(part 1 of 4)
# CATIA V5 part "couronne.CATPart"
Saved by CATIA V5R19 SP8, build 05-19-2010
Part number: couronne
Bounding box of the stored display mesh (mm): x 28.851 to 43.851, y 188.967 to 314.961, z 25.357 to 88.933
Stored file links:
  G:\EU_thinkMotion\CFAO_2010\MMS_groupe3\MMS_groupe3\A reprendre\amenand\amenand\couronne.CATPart
  F:\thinkmotion CFAO v12.1\essuie_glace.CATProduct
  G:\EU_thinkMotion\CFAO_2010\MMS_groupe3\MMS_groupe3\A reprendre\amenand\amenand\squelette_biellette3.CATPart
  CATDrawing1.CATDrawing
  G:\EU_thinkMotion\CFAO_2010\MMS_groupe3\MMS_groupe3\A reprendre\amenand\amenand\squelette_pignon.CATPart
  G:\EU_thinkMotion\CFAO_2010\MMS_groupe3\MMS_groupe3\A reprendre\amenand\amenand\bati.CATPart
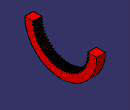
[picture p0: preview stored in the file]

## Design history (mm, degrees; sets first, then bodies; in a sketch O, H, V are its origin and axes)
Set1
  Plane1: linked copy from another document
  DatumCurve1 to DatumCurve3: linked copy from another document
Body1 (main body)
  Sketch1 on Plane1, origin (43.8512, 251.964, 88.354), H (0, 1, 0), V (0, 0, 1)
    point P1 (0, 0)
    line L1 (44.6312, -19.5831) -> (44.9349, -19.5977)
    line L2 (44.9349, -19.5977) -> (45.2527, -19.6074)
    line L3 (45.2527, -19.6074) -> (45.5845, -19.6118)
    line L4 (45.5845, -19.6118) -> (45.9303, -19.6103)
    line L5 (45.9303, -19.6103) -> (46.0835, -19.6069)
    arc A1 centre (46.029, -19.0968) radius 0.513 from (46.0835, -19.6069) to (46.1004, -19.6048) ccw
    arc A2 centre (45.9892, -19.104) radius 0.513 from (46.1004, -19.6048) to (46.1884, -19.5768) ccw
    arc A3 centre (45.9631, -19.1159) radius 0.513 from (46.1884, -19.5768) to (46.369, -19.4296) ccw
    arc A4 centre (45.9505, -19.1329) radius 0.513 from (46.369, -19.4296) to (46.419, -19.3418) ccw
    arc A5 centre (0, 0) radius 50.2875 from (46.419, -19.3419) to (46.5028, -19.1397) ccw
    arc A6 centre (46.0177, -18.9727) radius 0.513 from (46.5028, -19.1397) to (46.5269, -18.9102) ccw
    arc A7 centre (46.0212, -18.9965) radius 0.513 from (46.5269, -18.9102) to (46.4782, -18.7634) ccw
    arc A8 centre (46.0378, -19.0265) radius 0.513 from (46.4782, -18.7634) to (46.4517, -18.7234) ccw
    arc A9 centre (46.0672, -19.063) radius 0.513 from (46.4517, -18.7234) to (46.4347, -18.7051) ccw
    line L6 (46.4347, -18.7051) -> (46.2217, -18.4865)
    line L7 (46.2217, -18.4865) -> (45.9811, -18.248)
    line L8 (45.9811, -18.248) -> (45.7464, -18.0233)
    line L9 (45.7464, -18.0233) -> (45.5181, -17.8122)
    line L10 (45.5181, -17.8122) -> (45.2964, -17.6144)
    line L11 (45.2964, -17.6144) -> (45.0819, -17.4296)
    line L12 (45.0819, -17.4296) -> (44.8749, -17.2574)
    line L13 (44.8749, -17.2574) -> (44.6758, -17.0976)
    line L14 (44.6758, -17.0976) -> (44.4849, -16.9498)
    line L15 (44.4849, -16.9498) -> (44.3026, -16.8136)
    line L16 (44.3026, -16.8136) -> (44.1885, -16.7315)
    arc A10 centre (0, 0) radius 47.25 from (44.1885, -16.7315) to (44.605, -15.5869) ccw
    line L17 (44.605, -15.5869) -> (44.6371, -15.5896)
    line L18 (44.6371, -15.5896) -> (44.8572, -15.604)
    line L19 (44.8572, -15.604) -> (45.0914, -15.6153)
    line L20 (45.0914, -15.6153) -> (45.3396, -15.6228)
    line L21 (45.3396, -15.6228) -> (45.6019, -15.6263)
    line L22 (45.6019, -15.6263) -> (45.8781, -15.6251)
    line L23 (45.8781, -15.6251) -> (46.1681, -15.6187)
    line L24 (46.1681, -15.6187) -> (46.4719, -15.6068)
    line L25 (46.4719, -15.6068) -> (46.7894, -15.5888)
    line L26 (46.7894, -15.5888) -> (47.1203, -15.5642)
    line L27 (47.1203, -15.5642) -> (47.4646, -15.5326)
    line L28 (47.4646, -15.5326) -> (47.617, -15.5159)
    arc A11 centre (47.5182, -15.0125) radius 0.513 from (47.617, -15.5159) to (47.6336, -15.5123) ccw
    arc A12 centre (47.4792, -15.0231) radius 0.513 from (47.6336, -15.5123) to (47.7189, -15.4767) ccw
    arc A13 centre (47.4543, -15.0372) radius 0.513 from (47.7189, -15.4767) to (47.886, -15.3143) ccw
    arc A14 centre (47.4432, -15.0553) radius 0.513 from (47.886, -15.3143) to (47.9281, -15.2225) ccw
    arc A15 centre (0, 0) radius 50.2875 from (47.9281, -15.2225) to (47.9939, -15.0139) ccw
    arc A16 centre (47.4962, -14.8898) radius 0.513 from (47.9939, -15.0139) to (47.998, -14.7831) ccw
    arc A17 centre (47.5017, -14.9132) radius 0.513 from (47.998, -14.7831) to (47.9366, -14.6411) ccw
    arc A18 centre (47.5208, -14.9416) radius 0.513 from (47.9366, -14.6411) to (47.9068, -14.6036) ccw
    arc A19 centre (47.5534, -14.9755) radius 0.513 from (47.9068, -14.6036) to (47.8882, -14.5869) ccw
    line L29 (47.8882, -14.5869) -> (47.6571, -14.3877)
    line L30 (47.6571, -14.3877) -> (47.3966, -14.171)
    line L31 (47.3966, -14.171) -> (47.1432, -13.9677)
    line L32 (47.1432, -13.9677) -> (46.8973, -13.7773)
    line L33 (46.8973, -13.7773) -> (46.6593, -13.5995)
    line L34 (46.6593, -13.5995) -> (46.4295, -13.4341)
    line L35 (46.4295, -13.4341) -> (46.2082, -13.2806)
    line L36 (46.2082, -13.2806) -> (45.9959, -13.1388)
    line L37 (45.9959, -13.1388) -> (45.7929, -13.0081)
    line L38 (45.7929, -13.0081) -> (45.5994, -12.8884)
    line L39 (45.5994, -12.8884) -> (45.4786, -12.8165)
    arc A20 centre (0, 0) radius 47.25 from (45.4786, -12.8165) to (45.7938, -11.64) ccw
    line L40 (45.7938, -11.64) -> (45.8259, -11.6399)
    line L41 (45.8259, -11.6399) -> (46.0464, -11.6351)
    line L42 (46.0464, -11.6351) -> (46.2807, -11.6259)
    line L43 (46.2807, -11.6259) -> (46.5287, -11.6118)
    line L44 (46.5287, -11.6118) -> (46.7903, -11.5923)
    line L45 (46.7903, -11.5923) -> (47.0653, -11.5671)
    line L46 (47.0653, -11.5671) -> (47.3537, -11.5355)
    line L47 (47.3537, -11.5355) -> (47.6553, -11.4971)
    line L48 (47.6553, -11.4971) -> (47.97, -11.4515)
    line L49 (47.97, -11.4515) -> (48.2975, -11.3982)
    line L50 (48.2975, -11.3982) -> (48.6378, -11.3366)
    line L51 (48.6378, -11.3366) -> (48.7881, -11.3067)
    arc A21 centre (48.6458, -10.8139) radius 0.513 from (48.7881, -11.3067) to (48.8043, -11.3017) ccw
    arc A22 centre (48.6079, -10.8278) radius 0.513 from (48.8043, -11.3017) to (48.8862, -11.2588) ccw
    arc A23 centre (48.5843, -10.8441) radius 0.513 from (48.8862, -11.2588) to (49.0385, -11.0825) ccw
    arc A24 centre (48.5748, -10.863) radius 0.513 from (49.0385, -11.0825) to (49.0725, -10.9874) ccw
    arc A25 centre (0, 0) radius 50.2875 from (49.0725, -10.9874) to (49.1198, -10.7738) ccw
    arc A26 centre (48.6132, -10.6935) radius 0.513 from (49.1198, -10.7738) to (49.1037, -10.5436) ccw
    arc A27 centre (48.6207, -10.7164) radius 0.513 from (49.1037, -10.5436) to (49.0303, -10.4075) ccw
    arc A28 centre (48.6423, -10.743) radius 0.513 from (49.0303, -10.4075) to (48.9973, -10.3727) ccw
    arc A29 centre (48.6776, -10.7739) radius 0.513 from (48.9973, -10.3727) to (48.9773, -10.3576) ccw
    line L52 (48.9773, -10.3576) -> (48.7297, -10.1793)
    line L53 (48.7297, -10.1793) -> (48.4513, -9.9862)
    line L54 (48.4513, -9.9862) -> (48.1812, -9.8057)
    line L55 (48.1812, -9.8057) -> (47.9196, -9.6375)
    line L56 (47.9196, -9.6375) -> (47.667, -9.4811)
    line L57 (47.667, -9.4811) -> (47.4236, -9.3364)
    line L58 (47.4236, -9.3364) -> (47.1899, -9.2028)
    line L59 (47.1899, -9.2028) -> (46.966, -9.0799)
    line L60 (46.966, -9.0799) -> (46.7523, -8.9675)
    line L61 (46.7523, -8.9675) -> (46.5492, -8.8651)
    line L62 (46.5492, -8.8651) -> (46.4225, -8.804)
    arc A30 centre (0, 0) radius 47.25 from (46.4225, -8.804) to (46.634, -7.6046) ccw
    line L63 (46.634, -7.6045) -> (46.666, -7.6016)
    line L64 (46.666, -7.6016) -> (46.8853, -7.5776)
    line L65 (46.8853, -7.5776) -> (47.1179, -7.548)
    line L66 (47.1179, -7.548) -> (47.3637, -7.5124)
    line L67 (47.3637, -7.5124) -> (47.6226, -7.4702)
    line L68 (47.6226, -7.4702) -> (47.8944, -7.421)
    line L69 (47.8944, -7.421) -> (48.1789, -7.3644)
    line L70 (48.1789, -7.3644) -> (48.476, -7.2999)
    line L71 (48.476, -7.2999) -> (48.7855, -7.2271)
    line L72 (48.7855, -7.2271) -> (49.1071, -7.1454)
    line L73 (49.1071, -7.1454) -> (49.4407, -7.0544)
    line L74 (49.4407, -7.0544) -> (49.5879, -7.0115)
    arc A31 centre (49.4032, -6.5329) radius 0.513 from (49.5879, -7.0115) to (49.6036, -7.0052) ccw
    arc A32 centre (49.3666, -6.5502) radius 0.513 from (49.6036, -7.0052) to (49.6814, -6.9552) ccw
    arc A33 centre (49.3445, -6.5684) radius 0.513 from (49.6814, -6.9552) to (49.8178, -6.7664) ccw
    arc A34 centre (49.3367, -6.5881) radius 0.513 from (49.8178, -6.7664) to (49.8434, -6.6686) ccw
    arc A35 centre (0, 0) radius 50.2875 from (49.8434, -6.6686) to (49.8719, -6.4517) ccw
    arc A36 centre (49.3602, -6.4159) radius 0.513 from (49.8719, -6.4517) to (49.8358, -6.2238) ccw
    arc A37 centre (49.3697, -6.438) radius 0.513 from (49.8358, -6.2238) to (49.7508, -6.0946) ccw
    arc A38 centre (49.3935, -6.4627) radius 0.513 from (49.7508, -6.0946) to (49.7149, -6.0629) ccw
    arc A39 centre (49.4314, -6.4904) radius 0.513 from (49.7149, -6.0629) to (49.6937, -6.0495) ccw
    line L75 (49.6937, -6.0495) -> (49.4314, -5.8935)
    line L76 (49.4314, -5.8935) -> (49.1373, -5.7254)
    line L77 (49.1373, -5.7254) -> (48.8524, -5.5691)
    line L78 (48.8524, -5.5691) -> (48.5772, -5.4243)
    line L79 (48.5772, -5.4243) -> (48.3119, -5.2906)
    line L80 (48.3119, -5.2906) -> (48.0569, -5.1676)
    line L81 (48.0569, -5.1676) -> (47.8124, -5.0549)
    line L82 (47.8124, -5.0549) -> (47.5787, -4.952)
    line L83 (47.5787, -4.952) -> (47.356, -4.8587)
    line L84 (47.356, -4.8587) -> (47.1447, -4.7744)
    line L85 (47.1447, -4.7744) -> (47.0132, -4.7245)
    arc A40 centre (0, 0) radius 47.25 from (47.0132, -4.7246) to (47.1194, -3.5112) ccw
    line L86 (47.1194, -3.5112) -> (47.151, -3.5055)
    line L87 (47.151, -3.5055) -> (47.3673, -3.4624)
    line L88 (47.3673, -3.4624) -> (47.5964, -3.4127)
    line L89 (47.5964, -3.4127) -> (47.8382, -3.3558)
    line L90 (47.8382, -3.3558) -> (48.0924, -3.2912)
    line L91 (48.0924, -3.2912) -> (48.3589, -3.2185)
    line L92 (48.3589, -3.2185) -> (48.6374, -3.1374)
    line L93 (48.6374, -3.1374) -> (48.9278, -3.0472)
    line L94 (48.9278, -3.0472) -> (49.2297, -2.9476)
    line L95 (49.2297, -2.9476) -> (49.543, -2.8382)
    line L96 (49.543, -2.8382) -> (49.8674, -2.7185)
    line L97 (49.8674, -2.7185) -> (50.0103, -2.663)
    arc A41 centre (49.7846, -2.2023) radius 0.513 from (50.0103, -2.663) to (50.0254, -2.6553) ccw
    arc A42 centre (49.7497, -2.2227) radius 0.513 from (50.0254, -2.6553) to (50.0986, -2.5988) ccw
    arc A43 centre (49.7292, -2.2428) radius 0.513 from (50.0986, -2.5988) to (50.2179, -2.3987) ccw
    arc A44 centre (49.7232, -2.2631) radius 0.513 from (50.2179, -2.3987) to (50.2349, -2.2991) ccw
    arc A45 centre (0, 0) radius 50.2875 from (50.2349, -2.2991) to (50.2444, -2.0805) ccw
    arc A46 centre (49.7315, -2.0895) radius 0.513 from (50.2444, -2.0805) to (50.1886, -1.8566) ccw
    arc A47 centre (49.743, -2.1107) radius 0.513 from (50.1886, -1.8566) to (50.0926, -1.7353) ccw
    arc A48 centre (49.7688, -2.1332) radius 0.513 from (50.0926, -1.7353) to (50.0541, -1.7068) ccw
    arc A49 centre (49.809, -2.1575) radius 0.513 from (50.0541, -1.7068) to (50.0318, -1.6954) ccw
    line L98 (50.0318, -1.6954) -> (49.757, -1.5629)
    line L99 (49.757, -1.5629) -> (49.4493, -1.421)
    line L100 (49.4493, -1.421) -> (49.1519, -1.2902)
    line L101 (49.1519, -1.2902) -> (48.8651, -1.1699)
    line L102 (48.8651, -1.1699) -> (48.5892, -1.0598)
    line L103 (48.5892, -1.0598) -> (48.3244, -0.9595)
    line L104 (48.3244, -0.9595) -> (48.071, -0.8685)
    line L105 (48.071, -0.8685) -> (47.8292, -0.7864)
    line L106 (47.8292, -0.7864) -> (47.5993, -0.7128)
    line L107 (47.5993, -0.7128) -> (47.3814, -0.6473)
    line L108 (47.3814, -0.6473) -> (47.2461, -0.6091)
    arc A50 centre (0, 0) radius 47.25 from (47.2461, -0.6091) to (47.248, 0.434) ccw
    arc A51 centre (0, 0) radius 47.25 from (-47.248, -0.434) to (-47.2461, -0.6089) ccw
    line L109 (-47.2461, -0.6089) -> (-47.2771, -0.6174)
    line L110 (-47.2771, -0.6174) -> (-47.4888, -0.6791)
    line L111 (-47.4888, -0.6791) -> (-47.7127, -0.7486)
    line L112 (-47.7127, -0.7486) -> (-47.9486, -0.8264)
    line L113 (-47.9486, -0.8264) -> (-48.1963, -0.9129)
    line L114 (-48.1963, -0.9129) -> (-48.4554, -1.0085)
    line L115 (-48.4554, -1.0085) -> (-48.7258, -1.1136)
    line L116 (-48.7258, -1.1136) -> (-49.0072, -1.2287)
    line L117 (-49.0072, -1.2287) -> (-49.2993, -1.3542)
    line L118 (-49.2993, -1.3542) -> (-49.6019, -1.4905)
    line L119 (-49.6019, -1.4905) -> (-49.9146, -1.638)
    line L120 (-49.9146, -1.638) -> (-50.0521, -1.7058)
    arc A52 centre (-49.7871, -2.1451) radius 0.513 from (-50.0521, -1.7058) to (-50.0665, -1.7148) ccw
    arc A53 centre (-49.7541, -2.1217) radius 0.513 from (-50.0665, -1.7148) to (-50.1344, -1.7775) ccw
    arc A54 centre (-49.7354, -2.1) radius 0.513 from (-50.1344, -1.7775) to (-50.2359, -1.9872) ccw
    arc A55 centre (-49.7312, -2.0792) radius 0.513 from (-50.2359, -1.9872) to (-50.2441, -2.0879) ccw
    arc A56 centre (0, 0) radius 50.2875 from (-50.2441, -2.0879) to (-50.2346, -2.3065) ccw
    arc A57 centre (-49.7244, -2.2528) radius 0.513 from (-50.2346, -2.3065) to (-50.1595, -2.5247) ccw
    arc A58 centre (-49.7376, -2.2327) radius 0.513 from (-50.1595, -2.5247) to (-50.0532, -2.6371) ccw
    arc A59 centre (-49.7653, -2.2126) radius 0.513 from (-50.0532, -2.6371) to (-50.0124, -2.6622) ccw
    arc A60 centre (-49.8075, -2.1919) radius 0.513 from (-50.0124, -2.6622) to (-49.9892, -2.6716) ccw
    line L121 (-49.9892, -2.6716) -> (-49.7039, -2.7797)
    line L122 (-49.7039, -2.7797) -> (-49.385, -2.8942)
    line L123 (-49.385, -2.8942) -> (-49.0773, -2.9986)
    line L124 (-49.0773, -2.9986) -> (-48.7811, -3.0934)
    line L125 (-48.7811, -3.0934) -> (-48.4967, -3.179)
    line L126 (-48.4967, -3.179) -> (-48.2241, -3.2559)
    line L127 (-48.2241, -3.2559) -> (-47.9638, -3.3245)
    line L128 (-47.9638, -3.3245) -> (-47.7157, -3.3851)
    line L129 (-47.7157, -3.3851) -> (-47.4803, -3.4384)
    line L130 (-47.4803, -3.4384) -> (-47.2575, -3.4848)
    line L131 (-47.2575, -3.4848) -> (-47.1194, -3.511)
    arc A61 centre (0, 0) radius 47.25 from (-47.1194, -3.511) to (-47.0132, -4.7244) ccw
    line L132 (-47.0132, -4.7244) -> (-47.0434, -4.7355)
    line L133 (-47.0434, -4.7355) -> (-47.2489, -4.8154)
    line L134 (-47.2489, -4.8154) -> (-47.4659, -4.9042)
    line L135 (-47.4659, -4.9042) -> (-47.6941, -5.0022)
    line L136 (-47.6941, -5.0022) -> (-47.9333, -5.11)
    line L137 (-47.9333, -5.11) -> (-48.1831, -5.2278)
    line L138 (-48.1831, -5.2278) -> (-48.4433, -5.3561)
    line L139 (-48.4433, -5.3561) -> (-48.7136, -5.4953)
    line L140 (-48.7136, -5.4953) -> (-48.9937, -5.6458)
    line L141 (-48.9937, -5.6458) -> (-49.2832, -5.808)
    line L142 (-49.2832, -5.808) -> (-49.5819, -5.9822)
    line L143 (-49.5819, -5.9822) -> (-49.713, -6.0617)
    arc A62 centre (-49.4107, -6.4762) radius 0.513 from (-49.713, -6.0617) to (-49.7265, -6.0719) ccw
    arc A63 centre (-49.3798, -6.45) radius 0.513 from (-49.7265, -6.0719) to (-49.7887, -6.1403) ccw
    arc A64 centre (-49.3632, -6.4267) radius 0.513 from (-49.7887, -6.1403) to (-49.8715, -6.358) ccw
    arc A65 centre (-49.3608, -6.4057) radius 0.513 from (-49.8715, -6.358) to (-49.871, -6.459) ccw
    arc A66 centre (0, 0) radius 50.2875 from (-49.871, -6.459) to (-49.8424, -6.6759) ccw
    arc A67 centre (-49.3388, -6.578) radius 0.513 from (-49.8424, -6.6759) to (-49.7485, -6.8867) ccw
    arc A68 centre (-49.3538, -6.5591) radius 0.513 from (-49.7485, -6.8867) to (-49.6329, -6.9895) ccw
    arc A69 centre (-49.3831, -6.5415) radius 0.513 from (-49.6329, -6.9895) to (-49.59, -7.0109) ccw
    arc A70 centre (-49.4269, -6.5245) radius 0.513 from (-49.59, -7.0109) to (-49.5661, -7.0183) ccw
    line L144 (-49.5661, -7.0183) -> (-49.2725, -7.1011)
    line L145 (-49.2725, -7.1011) -> (-48.9448, -7.1873)
    line L146 (-48.9448, -7.1873) -> (-48.6292, -7.2646)
    line L147 (-48.6292, -7.2646) -> (-48.3259, -7.3332)
    line L148 (-48.3259, -7.3332) -> (-48.0351, -7.3937)
    line L149 (-48.0351, -7.3937) -> (-47.7569, -7.4465)
    line L150 (-47.7569, -7.4465) -> (-47.4915, -7.4921)
    line L151 (-47.4915, -7.4921) -> (-47.2391, -7.531)
    line L152 (-47.2391, -7.531) -> (-46.9999, -7.5635)
    line L153 (-46.9999, -7.5635) -> (-46.774, -7.5903)
    line L154 (-46.774, -7.5903) -> (-46.6341, -7.6043)
    arc A71 centre (0, 0) radius 47.25 from (-46.6341, -7.6044) to (-46.4226, -8.8039) ccw
    line L155 (-46.4226, -8.8039) -> (-46.4516, -8.8176)
    line L156 (-46.4516, -8.8176) -> (-46.6494, -8.9151)
    line L157 (-46.6494, -8.9151) -> (-46.8579, -9.0225)
    line L158 (-46.8579, -9.0225) -> (-47.0767, -9.14)
    line L159 (-47.0767, -9.14) -> (-47.3055, -9.2682)
    line L160 (-47.3055, -9.2682) -> (-47.5441, -9.4073)
    line L161 (-47.5441, -9.4073) -> (-47.7922, -9.5578)
    line L162 (-47.7922, -9.5578) -> (-48.0493, -9.7201)
    line L163 (-48.0493, -9.7201) -> (-48.3152, -9.8944)
    line L164 (-48.3152, -9.8944) -> (-48.5895, -10.0812)
    line L165 (-48.5895, -10.0812) -> (-48.8719, -10.2807)
    line L166 (-48.8719, -10.2807) -> (-48.9955, -10.3714)
    arc A72 centre (-48.6582, -10.7579) radius 0.513 from (-48.9955, -10.3714) to (-49.0081, -10.3827) ccw
    arc A73 centre (-48.6298, -10.7292) radius 0.513 from (-49.0081, -10.3827) to (-49.0641, -10.4563) ccw
    arc A74 centre (-48.6152, -10.7045) radius 0.513 from (-49.0641, -10.4563) to (-49.1276, -10.6804) ccw
    arc A75 centre (-48.6146, -10.6834) radius 0.513 from (-49.1276, -10.6804) to (-49.1183, -10.781) ccw
    arc A76 centre (0, 0) radius 50.2875 from (-49.1183, -10.781) to (-49.0709, -10.9946) ccw
    arc A77 centre (-48.5778, -10.8532) radius 0.513 from (-49.0709, -10.9946) to (-48.959, -11.1964) ccw
    arc A78 centre (-48.5943, -10.8356) radius 0.513 from (-48.959, -11.1964) to (-48.8349, -11.2887) ccw
    arc A79 centre (-48.6251, -10.8206) radius 0.513 from (-48.8349, -11.2887) to (-48.7903, -11.3063) ccw
    arc A80 centre (-48.6702, -10.8075) radius 0.513 from (-48.7903, -11.3063) to (-48.7658, -11.3115) ccw
    line L167 (-48.7658, -11.3115) -> (-48.4661, -11.3684)
    line L168 (-48.4661, -11.3684) -> (-48.1321, -11.4258)
    line L169 (-48.1321, -11.4258) -> (-47.811, -11.4752)
    line L170 (-47.811, -11.4752) -> (-47.5029, -11.5172)
    line L171 (-47.5029, -11.5172) -> (-47.2079, -11.5521)
    line L172 (-47.2079, -11.5521) -> (-46.9261, -11.5805)
    line L173 (-46.9261, -11.5805) -> (-46.6578, -11.6028)
    line L174 (-46.6578, -11.6028) -> (-46.403, -11.6195)
    line L175 (-46.403, -11.6195) -> (-46.1619, -11.631)
    line L176 (-46.1619, -11.631) -> (-45.9345, -11.638)
    line L177 (-45.9345, -11.638) -> (-45.7938, -11.6398)
    arc A81 centre (0, 0) radius 47.25 from (-45.7939, -11.6398) to (-45.4786, -12.8163) ccw
    line L178 (-45.4786, -12.8163) -> (-45.5064, -12.8325)
    line L179 (-45.5064, -12.8325) -> (-45.6949, -12.9469)
    line L180 (-45.6949, -12.9469) -> (-45.8932, -13.0721)
    line L181 (-45.8932, -13.0721) -> (-46.1009, -13.2083)
    line L182 (-46.1009, -13.2083) -> (-46.3177, -13.3559)
    line L183 (-46.3177, -13.3559) -> (-46.5433, -13.5153)
    line L184 (-46.5433, -13.5153) -> (-46.7773, -13.6868)
    line L185 (-46.7773, -13.6868) -> (-47.0193, -13.8709)
    line L186 (-47.0193, -13.8709) -> (-47.269, -14.0677)
    line L187 (-47.269, -14.0677) -> (-47.526, -14.2777)
    line L188 (-47.526, -14.2777) -> (-47.7899, -14.5011)
    line L189 (-47.7899, -14.5011) -> (-47.9051, -14.6021)
    arc A82 centre (-47.5354, -14.9578) radius 0.513 from (-47.9051, -14.6021) to (-47.9167, -14.6146) ccw
    arc A83 centre (-47.5096, -14.9268) radius 0.513 from (-47.9167, -14.6146) to (-47.9661, -14.6927) ccw
    arc A84 centre (-47.4972, -14.9009) radius 0.513 from (-47.9661, -14.6927) to (-48.0098, -14.9215) ccw
    arc A85 centre (-47.4985, -14.8798) radius 0.513 from (-48.0098, -14.9215) to (-47.9917, -15.0209) ccw
    arc A86 centre (0, 0) radius 50.2875 from (-47.9917, -15.0209) to (-47.9259, -15.2296) ccw
    arc A87 centre (-47.447, -15.0457) radius 0.513 from (-47.9259, -15.2296) to (-47.7969, -15.4209) ccw
    arc A88 centre (-47.465, -15.0297) radius 0.513 from (-47.7969, -15.4209) to (-47.6652, -15.502) ccw
    arc A89 centre (-47.497, -15.0174) radius 0.513 from (-47.6652, -15.502) to (-47.6192, -15.5156) ccw
    arc A90 centre (-47.543, -15.0083) radius 0.513 from (-47.6192, -15.5156) to (-47.5944, -15.5187) ccw
    line L190 (-47.5944, -15.5187) -> (-47.2908, -15.5493)
    line L191 (-47.2908, -15.5493) -> (-46.9532, -15.5773)
    line L192 (-46.9532, -15.5773) -> (-46.629, -15.5986)
    line L193 (-46.629, -15.5986) -> (-46.3183, -15.6135)
    line L194 (-46.3183, -15.6135) -> (-46.0214, -15.6226)
    line L195 (-46.0214, -15.6226) -> (-45.7383, -15.6263)
    line L196 (-45.7383, -15.6263) -> (-45.469, -15.6251)
    line L197 (-45.469, -15.6251) -> (-45.2137, -15.6195)
    line L198 (-45.2137, -15.6195) -> (-44.9725, -15.6101)
    line L199 (-44.9725, -15.6101) -> (-44.7453, -15.5972)
    line L200 (-44.7453, -15.5972) -> (-44.6051, -15.5867)
    arc A91 centre (0, 0) radius 47.25 from (-44.6051, -15.5867) to (-44.1885, -16.7313) ccw
    line L201 (-44.1885, -16.7313) -> (-44.2148, -16.7498)
    line L202 (-44.2148, -16.7498) -> (-44.3926, -16.8803)
    line L203 (-44.3926, -16.8803) -> (-44.5793, -17.0222)
    line L204 (-44.5793, -17.0222) -> (-44.7743, -17.176)
    line L205 (-44.7743, -17.176) -> (-44.9775, -17.3419)
    line L206 (-44.9775, -17.3419) -> (-45.1883, -17.5204)
    line L207 (-45.1883, -17.5204) -> (-45.4064, -17.7117)
    line L208 (-45.4064, -17.7117) -> (-45.6314, -17.9161)
    line L209 (-45.6314, -17.9161) -> (-45.863, -18.1339)
    line L210 (-45.863, -18.1339) -> (-46.1007, -18.3655)
    line L211 (-46.1007, -18.3655) -> (-46.3442, -18.6111)
    line L212 (-46.3442, -18.6111) -> (-46.4502, -18.7218)
    arc A92 centre (-46.0509, -19.0439) radius 0.513 from (-46.4502, -18.7218) to (-46.4606, -18.7352) ccw
    arc A93 centre (-46.0279, -19.0107) radius 0.513 from (-46.4606, -18.7352) to (-46.503, -18.8173) ccw
    arc A94 centre (-46.0178, -18.9838) radius 0.513 from (-46.503, -18.8173) to (-46.5266, -19.049) ccw
    arc A95 centre (-46.0209, -18.9629) radius 0.513 from (-46.5266, -19.049) to (-46.4999, -19.1465) ccw
    arc A96 centre (0, 0) radius 50.2875 from (-46.4999, -19.1465) to (-46.4162, -19.3486) ccw
    arc A97 centre (-45.9551, -19.1237) radius 0.513 from (-46.4162, -19.3486) to (-46.271, -19.5279) ccw
    arc A98 centre (-45.9744, -19.1093) radius 0.513 from (-46.271, -19.5279) to (-46.1327, -19.5973) ccw
    arc A99 centre (-46.0074, -19.0999) radius 0.513 from (-46.1327, -19.5973) to (-46.0858, -19.6068) ccw
    arc A100 centre (-46.054, -19.0948) radius 0.513 from (-46.0858, -19.6068) to (-46.0608, -19.6078) ccw
    line L213 (-46.0608, -19.6078) -> (-45.7556, -19.6118)
    line L214 (-45.7556, -19.6118) -> (-45.4168, -19.6103)
    line L215 (-45.4168, -19.6103) -> (-45.092, -19.6032)
    line L216 (-45.092, -19.6032) -> (-44.7813, -19.591)
    line L217 (-44.7813, -19.591) -> (-44.4847, -19.5742)
    line L218 (-44.4847, -19.5742) -> (-44.2023, -19.5532)
    line L219 (-44.2023, -19.5532) -> (-43.9342, -19.5285)
    line L220 (-43.9342, -19.5285) -> (-43.6803, -19.5007)
    line L221 (-43.6803, -19.5007) -> (-43.4409, -19.4703)
    line L222 (-43.4409, -19.4703) -> (-43.2157, -19.4376)
    line L223 (-43.2157, -19.4376) -> (-43.0769, -19.415)
    arc A101 centre (0, 0) radius 47.25 from (-43.0769, -19.415) to (-42.5622, -20.5189) ccw
    line L224 (-42.5622, -20.5189) -> (-42.5867, -20.5397)
    line L225 (-42.5867, -20.5397) -> (-42.7525, -20.6851)
    line L226 (-42.7525, -20.6851) -> (-42.9261, -20.8427)
    line L227 (-42.9261, -20.8427) -> (-43.107, -21.0129)
    line L228 (-43.107, -21.0129) -> (-43.2949, -21.196)
    line L229 (-43.2949, -21.196) -> (-43.4893, -21.3921)
    line L230 (-43.4893, -21.3921) -> (-43.6899, -21.6017)
    line L231 (-43.6899, -21.6017) -> (-43.8963, -21.8249)
    line L232 (-43.8963, -21.8249) -> (-44.108, -22.0622)
    line L233 (-44.108, -22.0622) -> (-44.3246, -22.3136)
    line L234 (-44.3246, -22.3136) -> (-44.5457, -22.5794)
    line L235 (-44.5457, -22.5794) -> (-44.6417, -22.6989)
    arc A102 centre (-44.2159, -22.985) radius 0.513 from (-44.6417, -22.6989) to (-44.6509, -22.7132) ccw
    arc A103 centre (-44.1958, -22.9499) radius 0.513 from (-44.6509, -22.7132) to (-44.686, -22.7987) ccw
    arc A104 centre (-44.1881, -22.9223) radius 0.513 from (-44.686, -22.7987) to (-44.6894, -23.0316) ccw
    arc A105 centre (-44.1931, -22.9017) radius 0.513 from (-44.6894, -23.0316) to (-44.6543, -23.1264) ccw
    arc A106 centre (0, 0) radius 50.2875 from (-44.6543, -23.1263) to (-44.5532, -23.3204) ccw
    arc A107 centre (-44.1135, -23.0562) radius 0.513 from (-44.5532, -23.3204) to (-44.3929, -23.4864) ccw
    arc A108 centre (-44.134, -23.0436) radius 0.513 from (-44.3929, -23.4864) to (-44.2491, -23.5435) ccw
    arc A109 centre (-44.1676, -23.037) radius 0.513 from (-44.2491, -23.5435) to (-44.2015, -23.5489) ccw
    arc A110 centre (-44.2146, -23.036) radius 0.513 from (-44.2015, -23.5489) to (-44.1766, -23.5476) ccw
    line L236 (-44.1766, -23.5476) -> (-43.8723, -23.525)
    line L237 (-43.8723, -23.525) -> (-43.5349, -23.494)
    line L238 (-43.5349, -23.494) -> (-43.2119, -23.4586)
    line L239 (-43.2119, -23.4586) -> (-42.9034, -23.4194)
    line L240 (-42.9034, -23.4194) -> (-42.6094, -23.3768)
    line L241 (-42.6094, -23.3768) -> (-42.3299, -23.3313)
    line L242 (-42.3299, -23.3313) -> (-42.065, -23.2833)
    line L243 (-42.065, -23.2833) -> (-41.8145, -23.2335)
    line L244 (-41.8145, -23.2335) -> (-41.5786, -23.1823)
    line L245 (-41.5786, -23.1823) -> (-41.3571, -23.1302)
    line L246 (-41.3571, -23.1302) -> (-41.2209, -23.0955)
    arc A111 centre (0, 0) radius 47.25 from (-41.2208, -23.0956) to (-40.6119, -24.1504) ccw
    line L247 (-40.6118, -24.1504) -> (-40.6345, -24.1732)
    line L248 (-40.6345, -24.1732) -> (-40.787, -24.3325)
    line L249 (-40.787, -24.3325) -> (-40.9461, -24.5047)
    line L250 (-40.9461, -24.5047) -> (-41.1115, -24.69)
    line L251 (-41.1115, -24.69) -> (-41.2828, -24.8887)
    line L252 (-41.2828, -24.8887) -> (-41.4594, -25.1011)
    line L253 (-41.4594, -25.1011) -> (-41.641, -25.3273)
    line L254 (-41.641, -25.3273) -> (-41.8271, -25.5677)
    line L255 (-41.8271, -25.5677) -> (-42.0173, -25.8225)
    line L256 (-42.0173, -25.8225) -> (-42.2112, -26.0918)
    line L257 (-42.2112, -26.0918) -> (-42.4083, -26.3759)
    line L258 (-42.4083, -26.3759) -> (-42.4935, -26.5033)
    arc A112 centre (-42.0443, -26.7512) radius 0.513 from (-42.4935, -26.5033) to (-42.5014, -26.5183) ccw
    arc A113 centre (-42.0274, -26.7145) radius 0.513 from (-42.5014, -26.5183) to (-42.5289, -26.6066) ccw
    arc A114 centre (-42.0222, -26.6863) radius 0.513 from (-42.5289, -26.6066) to (-42.512, -26.8389) ccw
    arc A115 centre (-42.0289, -26.6663) radius 0.513 from (-42.512, -26.8389) to (-42.4688, -26.9302) ccw
    arc A116 centre (0, 0) radius 50.2875 from (-42.4688, -26.9302) to (-42.3512, -27.1148) ccw
    arc A117 centre (-41.9362, -26.8132) radius 0.513 from (-42.3512, -27.1148) to (-42.177, -27.2661) ccw
    arc A118 centre (-41.9577, -26.8024) radius 0.513 from (-42.177, -27.2661) to (-42.0288, -27.3105) ccw
    arc A119 centre (-41.9918, -26.7988) radius 0.513 from (-42.0288, -27.3105) to (-41.9809, -27.3117) ccw
    arc A120 centre (-42.0386, -26.8019) radius 0.513 from (-41.9809, -27.3117) to (-41.9561, -27.3083) ccw
    line L259 (-41.9561, -27.3083) -> (-41.655, -27.2592)
    line L260 (-41.655, -27.2592) -> (-41.3216, -27.1989)
    line L261 (-41.3216, -27.1989) -> (-41.0029, -27.1355)
    line L262 (-41.0029, -27.1355) -> (-40.699, -27.0696)
    line L263 (-40.699, -27.0696) -> (-40.4098, -27.0015)
    line L264 (-40.4098, -27.0015) -> (-40.1354, -26.9318)
    line L265 (-40.1354, -26.9318) -> (-39.8756, -26.8609)
    line L266 (-39.8756, -26.8609) -> (-39.6305, -26.7895)
    line L267 (-39.6305, -26.7895) -> (-39.3999, -26.7179)
    line L268 (-39.3999, -26.7179) -> (-39.1838, -26.6466)
    line L269 (-39.1838, -26.6466) -> (-39.0511, -26.6003)
    arc A121 centre (0, 0) radius 47.25 from (-39.0511, -26.6003) to (-38.3525, -27.598) ccw
    line L270 (-38.3525, -27.598) -> (-38.373, -27.6227)
    line L271 (-38.373, -27.6227) -> (-38.5111, -27.7947)
    line L272 (-38.5111, -27.7947) -> (-38.6546, -27.9801)
    line L273 (-38.6546, -27.9801) -> (-38.8032, -28.1791)
    line L274 (-38.8032, -28.1791) -> (-38.9565, -28.392)
    line L275 (-38.9565, -28.392) -> (-39.1139, -28.619)
    line L276 (-39.1139, -28.619) -> (-39.2751, -28.8602)
    line L277 (-39.2751, -28.8602) -> (-39.4396, -29.1159)
    line L278 (-39.4396, -29.1159) -> (-39.6069, -29.3863)
    line L279 (-39.6069, -29.3863) -> (-39.7765, -29.6715)
    line L280 (-39.7765, -29.6715) -> (-39.9481, -29.9716)
    line L281 (-39.9481, -29.9716) -> (-40.0218, -30.106)
    arc A122 centre (-39.5528, -30.3138) radius 0.513 from (-40.0218, -30.106) to (-40.0285, -30.1217) ccw
    arc A123 centre (-39.5392, -30.2758) radius 0.513 from (-40.0285, -30.1217) to (-40.0482, -30.212) ccw
    arc A124 centre (-39.5364, -30.2473) radius 0.513 from (-40.0482, -30.212) to (-40.011, -30.4419) ccw
    arc A125 centre (-39.5448, -30.2278) radius 0.513 from (-40.011, -30.4419) to (-39.96, -30.5291) ccw
    arc A126 centre (0, 0) radius 50.2875 from (-39.96, -30.5291) to (-39.8268, -30.7027) ccw
    arc A127 centre (-39.4397, -30.3662) radius 0.513 from (-39.8268, -30.7027) to (-39.6401, -30.8384) ccw
    arc A128 centre (-39.462, -30.3573) radius 0.513 from (-39.6401, -30.8384) to (-39.4886, -30.8696) ccw
    arc A129 centre (-39.4963, -30.3566) radius 0.513 from (-39.4886, -30.8696) to (-39.4408, -30.8666) ccw
    arc A130 centre (-39.5427, -30.3638) radius 0.513 from (-39.4408, -30.8666) to (-39.4164, -30.8611) ccw
    line L282 (-39.4164, -30.8611) -> (-39.1207, -30.786)
    line L283 (-39.1207, -30.786) -> (-38.7938, -30.6968)
    line L284 (-38.7938, -30.6968) -> (-38.4819, -30.6059)
    line L285 (-38.4819, -30.6059) -> (-38.1849, -30.5137)
    line L286 (-38.1849, -30.5137) -> (-37.9027, -30.4207)
    line L287 (-37.9027, -30.4207) -> (-37.6354, -30.3273)
    line L288 (-37.6354, -30.3273) -> (-37.3828, -30.2341)
    line L289 (-37.3828, -30.2341) -> (-37.1448, -30.1416)
    line L290 (-37.1448, -30.1416) -> (-36.9214, -30.0502)
    line L291 (-36.9214, -30.0502) -> (-36.7123, -29.9603)
    line L292 (-36.7123, -29.9603) -> (-36.5841, -29.9026)
    arc A131 centre (0, 0) radius 47.25 from (-36.5841, -29.9026) to (-35.8012, -30.8356) ccw
    line L293 (-35.8012, -30.8356) -> (-35.8195, -30.862)
    line L294 (-35.8195, -30.862) -> (-35.942, -31.0454)
    line L295 (-35.942, -31.0454) -> (-36.0689, -31.2426)
    line L296 (-36.0689, -31.2426) -> (-36.1996, -31.4538)
    line L297 (-36.1996, -31.4538) -> (-36.3337, -31.6793)
    line L298 (-36.3337, -31.6793) -> (-36.4708, -31.9191)
    line L299 (-36.4708, -31.9191) -> (-36.6103, -32.1734)
    line L300 (-36.6103, -32.1734) -> (-36.7519, -32.4425)
    line L301 (-36.7519, -32.4425) -> (-36.895, -32.7264)
    line L302 (-36.895, -32.7264) -> (-37.0391, -33.0253)
    line L303 (-37.0391, -33.0253) -> (-37.1839, -33.3393)
    line L304 (-37.1839, -33.3393) -> (-37.2456, -33.4796)
    arc A132 centre (-36.7603, -33.6457) radius 0.513 from (-37.2456, -33.4796) to (-37.2509, -33.4958) ccw
    arc A133 centre (-36.75, -33.6067) radius 0.513 from (-37.2509, -33.4958) to (-37.2626, -33.5874) ccw
    arc A134 centre (-36.7497, -33.578) radius 0.513 from (-37.2626, -33.5874) to (-37.2056, -33.8133) ccw
    arc A135 centre (-36.7598, -33.5594) radius 0.513 from (-37.2056, -33.8133) to (-37.1472, -33.8957) ccw
    arc A136 centre (0, 0) radius 50.2875 from (-37.1472, -33.8957) to (-36.9993, -34.057) ccw
    arc A137 centre (-36.643, -33.688) radius 0.513 from (-36.9993, -34.057) to (-36.8016, -34.1759) ccw
    arc A138 centre (-36.6661, -33.6811) radius 0.513 from (-36.8016, -34.1759) to (-36.6479, -34.1938) ccw
    arc A139 centre (-36.7002, -33.6835) radius 0.513 from (-36.6479, -34.1938) to (-36.6005, -34.1867) ccw
    arc A140 centre (-36.7458, -33.6947) radius 0.513 from (-36.6005, -34.1867) to (-36.5767, -34.179) ccw
    line L305 (-36.5767, -34.179) -> (-36.2886, -34.0784)
    line L306 (-36.2886, -34.0784) -> (-35.9708, -33.9611)
    line L307 (-35.9708, -33.9611) -> (-35.6679, -33.8434)
    line L308 (-35.6679, -33.8434) -> (-35.3801, -33.7256)
    line L309 (-35.3801, -33.7256) -> (-35.1072, -33.6083)
    line L310 (-35.1072, -33.6083) -> (-34.849, -33.492)
    line L311 (-34.849, -33.492) -> (-34.6055, -33.3772)
    line L312 (-34.6055, -33.3772) -> (-34.3765, -33.2643)
    line L313 (-34.3765, -33.2643) -> (-34.1618, -33.1537)
    line L314 (-34.1618, -33.1537) -> (-33.9614, -33.046)
    line L315 (-33.9614, -33.046) -> (-33.8387, -32.9773)
    arc A141 centre (0, 0) radius 47.25 from (-33.8387, -32.9773) to (-32.9775, -33.8386) ccw
    line L316 (-32.9775, -33.8386) -> (-32.9934, -33.8665)
    line L317 (-32.9934, -33.8665) -> (-33.0995, -34.0598)
    line L318 (-33.0995, -34.0598) -> (-33.2087, -34.2674)
    line L319 (-33.2087, -34.2674) -> (-33.3205, -34.4892)
    line L320 (-33.3205, -34.4892) -> (-33.4344, -34.7254)
    line L321 (-33.4344, -34.7254) -> (-33.55, -34.9762)
    line L322 (-33.55, -34.9762) -> (-33.6669, -35.2418)
    line L323 (-33.6669, -35.2418) -> (-33.7845, -35.5222)
    line L324 (-33.7845, -35.5222) -> (-33.9023, -35.8175)
    line L325 (-33.9023, -35.8175) -> (-34.0199, -36.1278)
    line L326 (-34.0199, -36.1278) -> (-34.1367, -36.4532)
    line L327 (-34.1367, -36.4532) -> (-34.186, -36.5984)
    arc A142 centre (-33.688, -36.7216) radius 0.513 from (-34.186, -36.5984) to (-34.1898, -36.6149) ccw
    arc A143 centre (-33.6811, -36.6817) radius 0.513 from (-34.1898, -36.6149) to (-34.1935, -36.7073) ccw
    arc A144 centre (-33.6834, -36.6532) radius 0.513 from (-34.1935, -36.7073) to (-34.117, -36.9273) ccw
    arc A145 centre (-33.695, -36.6355) radius 0.513 from (-34.117, -36.9273) to (-34.0516, -37.0043) ccw
    arc A146 centre (0, 0) radius 50.2875 from (-34.0516, -37.0043) to (-33.8903, -37.1522) ccw
    arc A147 centre (-33.5674, -36.7535) radius 0.513 from (-33.8903, -37.1521) to (-33.6829, -37.2533) ccw
    arc A148 centre (-33.591, -36.7486) radius 0.513 from (-33.6829, -37.2533) to (-33.5283, -37.2577) ccw
    arc A149 centre (-33.6249, -36.7539) radius 0.513 from (-33.5283, -37.2577) to (-33.4817, -37.2465) ccw
    arc A150 centre (-33.6693, -36.7691) radius 0.513 from (-33.4817, -37.2465) to (-33.4586, -37.2368) ccw
    line L328 (-33.4586, -37.2368) -> (-33.1804, -37.1115)
    line L329 (-33.1804, -37.1115) -> (-32.874, -36.967)
    line L330 (-32.874, -36.967) -> (-32.5826, -36.8233)
    line L331 (-32.5826, -36.8233) -> (-32.3061, -36.6809)
    line L332 (-32.3061, -36.6809) -> (-32.0444, -36.5402)
    line L333 (-32.0444, -36.5402) -> (-31.7974, -36.4019)
    line L334 (-31.7974, -36.4019) -> (-31.5648, -36.2662)
    line L335 (-31.5648, -36.2662) -> (-31.3465, -36.1338)
    line L336 (-31.3465, -36.1338) -> (-31.1423, -36.005)
    line L337 (-31.1423, -36.005) -> (-30.952, -35.8802)
    line L338 (-30.952, -35.8802) -> (-30.8358, -35.8011)
    arc A151 centre (0, 0) radius 47.25 from (-30.8358, -35.8011) to (-29.9028, -36.584) ccw
    line L339 (-29.9027, -36.584) -> (-29.9162, -36.6132)
    line L340 (-29.9162, -36.6132) -> (-30.005, -36.815)
    line L341 (-30.005, -36.815) -> (-30.0957, -37.0313)
    line L342 (-30.0957, -37.0313) -> (-30.1877, -37.262)
    line L343 (-30.1877, -37.262) -> (-30.2807, -37.5073)
    line L344 (-30.2807, -37.5073) -> (-30.374, -37.7672)
    line L345 (-30.374, -37.7672) -> (-30.4673, -38.0419)
    line L346 (-30.4673, -38.0419) -> (-30.5599, -38.3315)
    line L347 (-30.5599, -38.3315) -> (-30.6516, -38.636)
    line L348 (-30.6516, -38.636) -> (-30.7417, -38.9553)
    line L349 (-30.7417, -38.9553) -> (-30.8297, -39.2897)
    line L350 (-30.8297, -39.2897) -> (-30.8661, -39.4386)
    arc A152 centre (-30.3593, -39.518) radius 0.513 from (-30.8661, -39.4386) to (-30.8685, -39.4554) ccw
    arc A153 centre (-30.3559, -39.4777) radius 0.513 from (-30.8685, -39.4554) to (-30.8641, -39.5478) ccw
    arc A154 centre (-30.3607, -39.4494) radius 0.513 from (-30.8641, -39.5478) to (-30.7687, -39.7603) ccw
    arc A155 centre (-30.3738, -39.4328) radius 0.513 from (-30.7687, -39.7603) to (-30.6969, -39.8313) ccw
    arc A156 centre (0, 0) radius 50.2875 from (-30.6969, -39.8313) to (-30.5233, -39.9645) ccw
    arc A157 centre (-30.2364, -39.5392) radius 0.513 from (-30.5233, -39.9645) to (-30.3079, -40.0472) ccw
    arc A158 centre (-30.2604, -39.5364) radius 0.513 from (-30.3079, -40.0472) to (-30.1534, -40.0381) ccw
    arc A159 centre (-30.2936, -39.5447) radius 0.513 from (-30.1534, -40.0381) to (-30.108, -40.0229) ccw
    arc A160 centre (-30.3366, -39.5636) radius 0.513 from (-30.108, -40.0229) to (-30.0859, -40.0112) ccw
    line L351 (-30.0859, -40.0112) -> (-29.8197, -39.8621)
    line L352 (-29.8197, -39.8621) -> (-29.527, -39.6914)
    line L353 (-29.527, -39.6914) -> (-29.2492, -39.5229)
    line L354 (-29.2492, -39.5229) -> (-28.9862, -39.3569)
    line L355 (-28.9862, -39.3569) -> (-28.7378, -39.1941)
    line L356 (-28.7378, -39.1941) -> (-28.5037, -39.0347)
    line L357 (-28.5037, -39.0347) -> (-28.2838, -38.8793)
    line L358 (-28.2838, -38.8793) -> (-28.0779, -38.7283)
    line L359 (-28.0779, -38.7283) -> (-27.8857, -38.5822)
    line L360 (-27.8857, -38.5822) -> (-27.7071, -38.4413)
    line L361 (-27.7071, -38.4413) -> (-27.5982, -38.3524)
    arc A161 centre (0, 0) radius 47.25 from (-27.5982, -38.3524) to (-26.6004, -39.051) ccw
    line L362 (-26.6004, -39.051) -> (-26.6113, -39.0812)
    line L363 (-26.6113, -39.0812) -> (-26.6822, -39.2901)
    line L364 (-26.6822, -39.2901) -> (-26.7537, -39.5134)
    line L365 (-26.7537, -39.5134) -> (-26.8253, -39.7512)
    line L366 (-26.8253, -39.7512) -> (-26.8965, -40.0037)
    line L367 (-26.8965, -40.0037) -> (-26.9668, -40.2708)
    line L368 (-26.9668, -40.2708) -> (-27.0357, -40.5526)
    line L369 (-27.0357, -40.5526) -> (-27.1028, -40.8491)
    line L370 (-27.1028, -40.8491) -> (-27.1676, -41.1604)
    line L371 (-27.1676, -41.1604) -> (-27.2295, -41.4864)
    line L372 (-27.2295, -41.4864) -> (-27.288, -41.8272)
    line L373 (-27.288, -41.8272) -> (-27.3114, -41.9787)
    arc A162 centre (-26.7995, -42.0136) radius 0.513 from (-27.3114, -41.9787) to (-27.3122, -41.9957) ccw
    arc A163 centre (-26.7997, -41.9731) radius 0.513 from (-27.3122, -41.9957) to (-27.2999, -42.0873) ccw
    arc A164 centre (-26.8069, -41.9454) radius 0.513 from (-27.2999, -42.0873) to (-27.1863, -42.2906) ccw
    arc A165 centre (-26.8215, -41.93) radius 0.513 from (-27.1863, -42.2906) to (-27.1086, -42.3551) ccw
    arc A166 centre (0, 0) radius 50.2875 from (-27.1086, -42.3551) to (-26.924, -42.4727) ccw
    arc A167 centre (-26.6753, -42.024) radius 0.513 from (-26.924, -42.4727) to (-26.7022, -42.5363) ccw
    arc A168 centre (-26.6994, -42.0233) radius 0.513 from (-26.7022, -42.5363) to (-26.5491, -42.5138) ccw
    arc A169 centre (-26.7318, -42.0344) radius 0.513 from (-26.5491, -42.5138) to (-26.5052, -42.4947) ccw
    arc A170 centre (-26.7729, -42.0571) radius 0.513 from (-26.5052, -42.4947) to (-26.4842, -42.4811) ccw
    line L374 (-26.4842, -42.4811) -> (-26.232, -42.3094)
    line L375 (-26.232, -42.3094) -> (-25.9553, -42.1138)
    line L376 (-25.9553, -42.1138) -> (-25.6933, -41.9217)
    line L377 (-25.6933, -41.9217) -> (-25.4457, -41.7335)
    line L378 (-25.4457, -41.7335) -> (-25.2124, -41.5496)
    line L379 (-25.2124, -41.5496) -> (-24.9932, -41.3704)
    line L380 (-24.9932, -41.3704) -> (-24.7877, -41.1964)
    line L381 (-24.7877, -41.1964) -> (-24.5957, -41.0281)
    line L382 (-24.5957, -41.0281) -> (-24.417, -40.8658)
    line L383 (-24.417, -40.8658) -> (-24.2513, -40.7099)
    line L384 (-24.2513, -40.7099) -> (-24.1505, -40.6118)
    arc A171 centre (0, 0) radius 47.25 from (-24.1505, -40.6118) to (-23.0957, -41.2208) ccw
    line L385 (-23.0957, -41.2208) -> (-23.1039, -41.2518)
    line L386 (-23.1039, -41.2518) -> (-23.1563, -41.4661)
    line L387 (-23.1563, -41.4661) -> (-23.2081, -41.6948)
    line L388 (-23.2081, -41.6948) -> (-23.2586, -41.9379)
    line L389 (-23.2586, -41.9379) -> (-23.3076, -42.1956)
    line L390 (-23.3076, -42.1956) -> (-23.3543, -42.4678)
    line L391 (-23.3543, -42.4678) -> (-23.3985, -42.7546)
    line L392 (-23.3985, -42.7546) -> (-23.4395, -43.0558)
    line L393 (-23.4395, -43.0558) -> (-23.4768, -43.3716)
    line L394 (-23.4768, -43.3716) -> (-23.5101, -43.7018)
    line L395 (-23.5101, -43.7018) -> (-23.5387, -44.0463)
    line L396 (-23.5387, -44.0463) -> (-23.5487, -44.1993)
    arc A172 centre (-23.0358, -44.1894) radius 0.513 from (-23.5487, -44.1993) to (-23.5481, -44.2163) ccw
    arc A173 centre (-23.0395, -44.1492) radius 0.513 from (-23.5481, -44.2163) to (-23.5278, -44.3064) ccw
    arc A174 centre (-23.0491, -44.1221) radius 0.513 from (-23.5278, -44.3064) to (-23.397, -44.4992) ccw
    arc A175 centre (-23.065, -44.1081) radius 0.513 from (-23.397, -44.4992) to (-23.3139, -44.5566) ccw
    arc A176 centre (0, 0) radius 50.2875 from (-23.3139, -44.5566) to (-23.1198, -44.6577) ccw
    arc A177 centre (-22.9112, -44.189) radius 0.513 from (-23.1198, -44.6577) to (-22.8933, -44.7017) ccw
    arc A178 centre (-22.9352, -44.1904) radius 0.513 from (-22.8933, -44.7017) to (-22.7428, -44.666) ccw
    arc A179 centre (-22.9665, -44.2043) radius 0.513 from (-22.7428, -44.666) to (-22.7007, -44.6431) ccw
    arc A180 centre (-23.0055, -44.2305) radius 0.513 from (-22.7007, -44.6431) to (-22.6809, -44.6277) ccw
    line L397 (-22.6809, -44.6277) -> (-22.4447, -44.4347)
    line L398 (-22.4447, -44.4347) -> (-22.1861, -44.2157)
    line L399 (-22.1861, -44.2157) -> (-21.9418, -44.0015)
    line L400 (-21.9418, -44.0015) -> (-21.7116, -43.7924)
    line L401 (-21.7116, -43.7924) -> (-21.4952, -43.5889)
    line L402 (-21.4952, -43.5889) -> (-21.2924, -43.3913)
    line L403 (-21.2924, -43.3913) -> (-21.1028, -43.2001)
    line L404 (-21.1028, -43.2001) -> (-20.9263, -43.0156)
    line L405 (-20.9263, -43.0156) -> (-20.7624, -42.8383)
    line L406 (-20.7624, -42.8383) -> (-20.6109, -42.6686)
    line L407 (-20.6109, -42.6686) -> (-20.5191, -42.5621)
    arc A181 centre (0, 0) radius 47.25 from (-20.5191, -42.5621) to (-19.4152, -43.0768) ccw
    line L408 (-19.4152, -43.0768) -> (-19.4206, -43.1085)
    line L409 (-19.4206, -43.1085) -> (-19.4542, -43.3265)
    line L410 (-19.4542, -43.3265) -> (-19.4858, -43.5588)
    line L411 (-19.4858, -43.5588) -> (-19.515, -43.8055)
    line L412 (-19.515, -43.8055) -> (-19.5413, -44.0664)
    line L413 (-19.5413, -44.0664) -> (-19.5642, -44.3417)
    line L414 (-19.5642, -44.3417) -> (-19.5831, -44.6312)
    line L415 (-19.5831, -44.6312) -> (-19.5977, -44.9349)
    line L416 (-19.5977, -44.9349) -> (-19.6074, -45.2527)
    line L417 (-19.6074, -45.2527) -> (-19.6118, -45.5845)
    line L418 (-19.6118, -45.5845) -> (-19.6103, -45.9303)
    line L419 (-19.6103, -45.9303) -> (-19.6069, -46.0835)
    arc A182 centre (-19.0968, -46.029) radius 0.513 from (-19.6069, -46.0835) to (-19.6048, -46.1004) ccw
    arc A183 centre (-19.104, -45.9892) radius 0.513 from (-19.6048, -46.1004) to (-19.5768, -46.1884) ccw
    arc A184 centre (-19.1159, -45.9631) radius 0.513 from (-19.5768, -46.1884) to (-19.4296, -46.369) ccw
    arc A185 centre (-19.1329, -45.9505) radius 0.513 from (-19.4296, -46.369) to (-19.3418, -46.419) ccw
    arc A186 centre (0, 0) radius 50.2875 from (-19.3418, -46.419) to (-19.1397, -46.5027) ccw
    arc A187 centre (-18.9727, -46.0177) radius 0.513 from (-19.1397, -46.5028) to (-18.9102, -46.5269) ccw
    arc A188 centre (-18.9965, -46.0212) radius 0.513 from (-18.9102, -46.5269) to (-18.7634, -46.4782) ccw
    arc A189 centre (-19.0265, -46.0378) radius 0.513 from (-18.7634, -46.4782) to (-18.7234, -46.4517) ccw
    arc A190 centre (-19.063, -46.0672) radius 0.513 from (-18.7234, -46.4517) to (-18.7051, -46.4347) ccw
    line L420 (-18.7051, -46.4347) -> (-18.4865, -46.2217)
    line L421 (-18.4865, -46.2217) -> (-18.248, -45.9811)
    line L422 (-18.248, -45.9811) -> (-18.0233, -45.7464)
    line L423 (-18.0233, -45.7464) -> (-17.8122, -45.5181)
    line L424 (-17.8122, -45.5181) -> (-17.6144, -45.2964)
    line L425 (-17.6144, -45.2964) -> (-17.4296, -45.0819)
    line L426 (-17.4296, -45.0819) -> (-17.2574, -44.8749)
    line L427 (-17.2574, -44.8749) -> (-17.0976, -44.6758)
    line L428 (-17.0976, -44.6758) -> (-16.9498, -44.4849)
    line L429 (-16.9498, -44.4849) -> (-16.8136, -44.3026)
    line L430 (-16.8136, -44.3026) -> (-16.7315, -44.1885)
    arc A191 centre (0, 0) radius 47.25 from (-16.7315, -44.1885) to (-15.5869, -44.605) ccw
    line L431 (-15.5869, -44.605) -> (-15.5896, -44.6371)
    line L432 (-15.5896, -44.6371) -> (-15.604, -44.8572)
    line L433 (-15.604, -44.8572) -> (-15.6153, -45.0914)
    line L434 (-15.6153, -45.0914) -> (-15.6228, -45.3396)
    line L435 (-15.6228, -45.3396) -> (-15.6263, -45.6019)
    line L436 (-15.6263, -45.6019) -> (-15.6251, -45.8781)
    line L437 (-15.6251, -45.8781) -> (-15.6187, -46.1681)
    line L438 (-15.6187, -46.1681) -> (-15.6068, -46.4719)
    line L439 (-15.6068, -46.4719) -> (-15.5888, -46.7894)
    line L440 (-15.5888, -46.7894) -> (-15.5642, -47.1203)
    line L441 (-15.5642, -47.1203) -> (-15.5326, -47.4646)
    line L442 (-15.5326, -47.4646) -> (-15.5159, -47.617)
    arc A192 centre (-15.0125, -47.5182) radius 0.513 from (-15.5159, -47.617) to (-15.5123, -47.6336) ccw
    arc A193 centre (-15.0231, -47.4792) radius 0.513 from (-15.5123, -47.6336) to (-15.4767, -47.7189) ccw
    arc A194 centre (-15.0372, -47.4543) radius 0.513 from (-15.4767, -47.7189) to (-15.3143, -47.886) ccw
    arc A195 centre (-15.0553, -47.4432) radius 0.513 from (-15.3143, -47.886) to (-15.2225, -47.9281) ccw
    arc A196 centre (0, 0) radius 50.2875 from (-15.2225, -47.9281) to (-15.0138, -47.9939) ccw
    arc A197 centre (-14.8898, -47.4962) radius 0.513 from (-15.0139, -47.9939) to (-14.7831, -47.998) ccw
    arc A198 centre (-14.9132, -47.5017) radius 0.513 from (-14.7831, -47.998) to (-14.6411, -47.9366) ccw
    arc A199 centre (-14.9416, -47.5208) radius 0.513 from (-14.6411, -47.9366) to (-14.6036, -47.9068) ccw
    arc A200 centre (-14.9755, -47.5534) radius 0.513 from (-14.6036, -47.9068) to (-14.5869, -47.8882) ccw
    line L443 (-14.5869, -47.8882) -> (-14.3877, -47.6571)
    line L444 (-14.3877, -47.6571) -> (-14.171, -47.3966)
    line L445 (-14.171, -47.3966) -> (-13.9677, -47.1432)
    line L446 (-13.9677, -47.1432) -> (-13.7773, -46.8973)
    line L447 (-13.7773, -46.8973) -> (-13.5995, -46.6593)
    line L448 (-13.5995, -46.6593) -> (-13.4341, -46.4295)
    line L449 (-13.4341, -46.4295) -> (-13.2806, -46.2082)
    line L450 (-13.2806, -46.2082) -> (-13.1388, -45.9959)
    line L451 (-13.1388, -45.9959) -> (-13.0081, -45.7929)
    line L452 (-13.0081, -45.7929) -> (-12.8884, -45.5994)
    line L453 (-12.8884, -45.5994) -> (-12.8165, -45.4786)
    arc A201 centre (0, 0) radius 47.25 from (-12.8165, -45.4786) to (-11.64, -45.7938) ccw
    line L454 (-11.64, -45.7938) -> (-11.6399, -45.8259)
    line L455 (-11.6399, -45.8259) -> (-11.6351, -46.0464)
    line L456 (-11.6351, -46.0464) -> (-11.6259, -46.2807)
    line L457 (-11.6259, -46.2807) -> (-11.6118, -46.5287)
    line L458 (-11.6118, -46.5287) -> (-11.5923, -46.7903)
    line L459 (-11.5923, -46.7903) -> (-11.5671, -47.0653)
    line L460 (-11.5671, -47.0653) -> (-11.5355, -47.3537)
    line L461 (-11.5355, -47.3537) -> (-11.4971, -47.6553)
    line L462 (-11.4971, -47.6553) -> (-11.4515, -47.97)
    line L463 (-11.4515, -47.97) -> (-11.3982, -48.2975)
    line L464 (-11.3982, -48.2975) -> (-11.3366, -48.6378)
    line L465 (-11.3366, -48.6378) -> (-11.3067, -48.7881)
    arc A202 centre (-10.8139, -48.6458) radius 0.513 from (-11.3067, -48.7881) to (-11.3017, -48.8043) ccw
    arc A203 centre (-10.8278, -48.6079) radius 0.513 from (-11.3017, -48.8043) to (-11.2588, -48.8862) ccw
    arc A204 centre (-10.8441, -48.5843) radius 0.513 from (-11.2588, -48.8862) to (-11.0825, -49.0385) ccw
    arc A205 centre (-10.863, -48.5748) radius 0.513 from (-11.0825, -49.0385) to (-10.9874, -49.0725) ccw
    arc A206 centre (0, 0) radius 50.2875 from (-10.9874, -49.0725) to (-10.7738, -49.1198) ccw
    arc A207 centre (-10.6935, -48.6132) radius 0.513 from (-10.7738, -49.1198) to (-10.5436, -49.1037) ccw
    arc A208 centre (-10.7164, -48.6207) radius 0.513 from (-10.5436, -49.1037) to (-10.4075, -49.0303) ccw
    arc A209 centre (-10.743, -48.6423) radius 0.513 from (-10.4075, -49.0303) to (-10.3727, -48.9973) ccw
    arc A210 centre (-10.7739, -48.6776) radius 0.513 from (-10.3727, -48.9973) to (-10.3576, -48.9773) ccw
    line L466 (-10.3576, -48.9773) -> (-10.1793, -48.7297)
    line L467 (-10.1793, -48.7297) -> (-9.9862, -48.4513)
    line L468 (-9.9862, -48.4513) -> (-9.8057, -48.1812)
    line L469 (-9.8057, -48.1812) -> (-9.6375, -47.9196)
    line L470 (-9.6375, -47.9196) -> (-9.4811, -47.667)
    line L471 (-9.4811, -47.667) -> (-9.3364, -47.4236)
